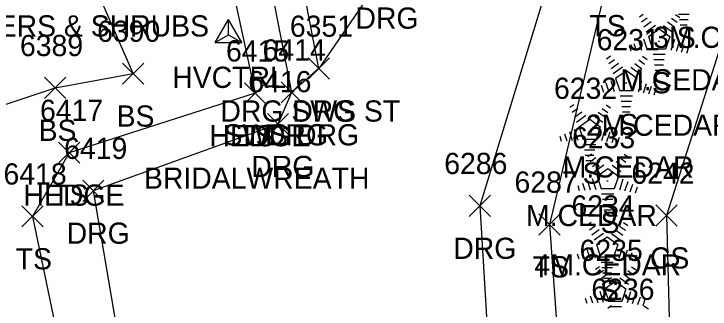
# Model space of a CAD drawing. Extents: x 1472233 to 1475777, y 540726 to 543442.
# Drawn here: x 1472325.6 to 1472391.2, y 541713.6 to 541741.4 of the extents above; entities that cross this region are included whole.
import ezdxf

# ---------------------------------------------------------------- set-up
doc = ezdxf.new("R2010")
doc.units = 0
for name, color, linetype in [('C_A', 7, 'Continuous'), ('CPSM', 7, 'Continuous'), ('L_A', 7, 'Continuous'), ('L_C', 7, 'Continuous'), ('L_I', 7, 'Continuous'), ('L_TIC', 7, 'Continuous'), ('LAHR', 7, 'Continuous'), ('LELB', 7, 'Continuous'), ('LTC', 7, 'Continuous'), ('R_A', 7, 'Continuous'), ('R_I', 7, 'Continuous'), ('R_TIC', 7, 'Continuous'), ('RDG', 7, 'Continuous'), ('RSW', 7, 'Continuous')]:
    doc.layers.add(name, color=color, linetype=linetype)

msp = doc.modelspace()

# ---------------------------------------------------------------- linework, layer by layer
at = {"layer": 'CPSM'}
for p, q in [((1472344.546, 541738.709), (1472345.796, 541740.875)), ((1472347.046, 541738.709), (1472345.796, 541740.875)), ((1472345.796, 541739.431), (1472345.796, 541740.875)), ((1472344.546, 541738.709), (1472345.796, 541739.431)), ((1472345.796, 541739.431), (1472345.796, 541739.431)), ((1472345.796, 541739.431), (1472347.046, 541738.709)), ((1472344.546, 541738.709), (1472347.046, 541738.709))]:
    msp.add_line(p, q, dxfattribs=at)
at = {"layer": 'L_TIC'}
for points in [[(1472335.805, 541734.776), (1472337.805, 541736.776)], [(1472337.805, 541734.776), (1472335.805, 541736.776)], [(1472328.455, 541733.43), (1472330.455, 541735.43)], [(1472330.455, 541733.43), (1472328.455, 541735.43)], [(1472347.293, 541732.92), (1472349.293, 541734.92)], [(1472349.293, 541732.92), (1472347.293, 541734.92)], [(1472347.293, 541732.92), (1472349.293, 541734.92)], [(1472349.293, 541732.92), (1472347.293, 541734.92)], [(1472329.773, 541727.319), (1472331.773, 541729.319)], [(1472331.773, 541727.319), (1472329.773, 541729.319)], [(1472329.773, 541727.319), (1472331.773, 541729.319)], [(1472331.773, 541727.319), (1472329.773, 541729.319)], [(1472326.33, 541721.315), (1472328.33, 541723.315)], [(1472328.33, 541721.315), (1472326.33, 541723.315)], [(1472386.055, 541721.394), (1472388.055, 541723.394)], [(1472388.055, 541721.394), (1472386.055, 541723.394)], [(1472375.043, 541720.552), (1472377.043, 541722.552)], [(1472377.043, 541720.552), (1472375.043, 541722.552)]]:
    msp.add_lwpolyline(points, dxfattribs=at)
at = {"layer": 'LAHR'}
msp.add_lwpolyline([(1472348.293, 541733.92), (1472330.773, 541728.319)], dxfattribs=at)
at = {"layer": 'LELB'}
for points in [[(1472436.391, 541801.492), (1472421.411, 541789.524), (1472401.228, 541772.53), (1472387.568, 541756.153), (1472381.39, 541744.301), (1472376.043, 541721.552), (1472378.297, 541690.008), (1472384.499, 541660.373), (1472385.476, 541622.917), (1472385.225, 541602.047), (1472389.103, 541583.282), (1472392.292, 541571.183), (1472400.004, 541561.87), (1472414.969, 541552.967), (1472430.215, 541550.577), (1472460.47, 541554.643), (1472482.624, 541564.355)], [(1472336.689, 541778.111), (1472339.985, 541776.003), (1472343.517, 541755.985), (1472348.293, 541733.92)], [(1472456.456, 541773.785), (1472441.328, 541777.081), (1472419.974, 541764.524), (1472393.226, 541741.709), (1472387.055, 541722.394), (1472387.861, 541691.003), (1472394.403, 541676.497), (1472412.587, 541665.699), (1472419.922, 541640.116), (1472426.411, 541618.317)], [(1472319.347, 541731.083), (1472329.455, 541734.43), (1472336.805, 541735.776), (1472331.369, 541748.277)], [(1472330.773, 541728.319), (1472327.33, 541722.315), (1472334.368, 541688.443), (1472342.801, 541683.722), (1472358.1, 541689.107)]]:
    msp.add_lwpolyline(points, dxfattribs=at)
at = {"layer": 'LTC'}
for p, q in [((1472384.498, 541741.122), (1472384.853, 541741.38)), ((1472384.708, 541740.657), (1472385.237, 541741.041)), ((1472387.525, 541741.014), (1472388.075, 541740.615)), ((1472387.897, 541741.363), (1472388.316, 541741.058)), ((1472389.184, 541741.36), (1472388.195, 541741.36)), ((1472384.917, 541740.191), (1472385.621, 541740.702)), ((1472385.127, 541739.725), (1472386.005, 541740.363)), ((1472387.154, 541740.666), (1472387.834, 541740.172)), ((1472389.1, 541740.86), (1472388.268, 541740.86)), ((1472389.016, 541740.36), (1472388.341, 541740.36)), ((1472385.352, 541739.27), (1472386.363, 541740.005)), ((1472386.363, 541740.005), (1472387.36, 541739.28)), ((1472386.783, 541740.318), (1472387.593, 541739.729)), ((1472384.897, 541739.051), (1472385.228, 541738.032)), ((1472385.352, 541739.27), (1472385.739, 541738.077)), ((1472387.36, 541739.28), (1472386.969, 541738.077)), ((1472383.531, 541738.401), (1472383.683, 541737.933)), ((1472383.986, 541738.618), (1472384.198, 541737.966)), ((1472384.442, 541738.835), (1472384.713, 541737.999)), ((1472387.798, 541739.009), (1472387.46, 541737.969)), ((1472388.242, 541738.758), (1472387.955, 541737.874)), ((1472388.687, 541738.508), (1472388.45, 541737.779)), ((1472386.969, 541738.077), (1472385.739, 541738.077)), ((1472389.131, 541738.258), (1472388.944, 541737.684)), ((1472381.41, 541737.186), (1472381.765, 541737.444)), ((1472381.62, 541736.721), (1472382.149, 541737.105)), ((1472384.437, 541737.078), (1472384.987, 541736.679)), ((1472384.809, 541737.427), (1472385.228, 541737.122)), ((1472386.931, 541737.577), (1472385.786, 541737.577)), ((1472386.847, 541737.077), (1472385.859, 541737.077)), ((1472381.829, 541736.255), (1472382.533, 541736.766)), ((1472382.039, 541735.789), (1472382.917, 541736.427)), ((1472384.067, 541736.73), (1472384.746, 541736.236)), ((1472386.763, 541736.577), (1472385.932, 541736.577)), ((1472382.264, 541735.334), (1472383.275, 541736.069)), ((1472383.275, 541736.069), (1472384.272, 541735.344)), ((1472383.695, 541736.382), (1472384.505, 541735.793)), ((1472386.679, 541736.077), (1472386.004, 541736.077)), ((1472381.809, 541735.115), (1472382.14, 541734.096)), ((1472382.264, 541735.334), (1472382.651, 541734.141)), ((1472384.272, 541735.344), (1472383.881, 541734.141)), ((1472380.443, 541734.465), (1472380.595, 541733.998)), ((1472380.898, 541734.682), (1472381.11, 541734.03)), ((1472381.354, 541734.899), (1472381.625, 541734.063)), ((1472384.71, 541735.073), (1472384.372, 541734.033)), ((1472385.154, 541734.823), (1472384.867, 541733.938)), ((1472385.599, 541734.573), (1472385.362, 541733.843)), ((1472383.881, 541734.141), (1472382.651, 541734.141)), ((1472386.043, 541734.322), (1472385.857, 541733.748)), ((1472383.843, 541733.641), (1472382.698, 541733.641)), ((1472383.759, 541733.141), (1472382.771, 541733.141)), ((1472377.96, 541732.606), (1472378.315, 541732.863)), ((1472378.17, 541732.14), (1472378.699, 541732.524)), ((1472380.987, 541732.498), (1472381.537, 541732.099)), ((1472381.359, 541732.846), (1472381.778, 541732.542)), ((1472383.675, 541732.641), (1472382.844, 541732.641)), ((1472378.379, 541731.674), (1472379.083, 541732.186)), ((1472378.589, 541731.209), (1472379.467, 541731.847)), ((1472380.617, 541732.149), (1472381.296, 541731.656)), ((1472383.592, 541732.141), (1472382.917, 541732.141)), ((1472378.814, 541730.754), (1472379.825, 541731.488)), ((1472379.825, 541731.488), (1472380.822, 541730.763)), ((1472380.245, 541731.801), (1472381.055, 541731.212)), ((1472378.359, 541730.534), (1472378.69, 541729.515)), ((1472378.814, 541730.754), (1472379.201, 541729.56)), ((1472380.822, 541730.763), (1472380.431, 541729.56)), ((1472376.993, 541729.885), (1472377.145, 541729.417)), ((1472377.448, 541730.102), (1472377.66, 541729.45)), ((1472377.904, 541730.318), (1472378.175, 541729.483)), ((1472381.26, 541730.492), (1472380.922, 541729.453)), ((1472381.704, 541730.242), (1472381.417, 541729.357)), ((1472382.149, 541729.992), (1472381.912, 541729.262)), ((1472380.431, 541729.56), (1472379.201, 541729.56)), ((1472382.593, 541729.742), (1472382.407, 541729.167)), ((1472380.393, 541729.06), (1472379.248, 541729.06)), ((1472380.309, 541728.56), (1472379.321, 541728.56)), ((1472380.225, 541728.06), (1472379.394, 541728.06)), ((1472379.657, 541727.948), (1472380.011, 541728.205)), ((1472383.055, 541728.188), (1472383.474, 541727.883)), ((1472380.142, 541727.56), (1472379.467, 541727.56)), ((1472379.866, 541727.482), (1472380.395, 541727.866)), ((1472380.076, 541727.016), (1472380.78, 541727.528)), ((1472382.313, 541727.491), (1472382.992, 541726.998)), ((1472382.684, 541727.84), (1472383.233, 541727.44)), ((1472380.285, 541726.55), (1472381.164, 541727.188)), ((1472380.51, 541726.095), (1472381.522, 541726.83)), ((1472381.522, 541726.83), (1472382.519, 541726.105)), ((1472381.942, 541727.143), (1472382.751, 541726.554)), ((1472380.51, 541726.095), (1472380.897, 541724.902)), ((1472382.519, 541726.105), (1472382.127, 541724.902)), ((1472379.145, 541725.443), (1472379.356, 541724.792)), ((1472379.6, 541725.66), (1472379.871, 541724.825)), ((1472380.055, 541725.876), (1472380.386, 541724.857)), ((1472382.956, 541725.834), (1472382.618, 541724.795)), ((1472383.401, 541725.584), (1472383.113, 541724.699)), ((1472383.845, 541725.334), (1472383.608, 541724.604)), ((1472378.689, 541725.227), (1472378.841, 541724.759)), ((1472382.127, 541724.902), (1472380.897, 541724.902)), ((1472384.29, 541725.083), (1472384.103, 541724.509)), ((1472382.089, 541724.402), (1472380.945, 541724.402)), ((1472382.005, 541723.902), (1472381.017, 541723.902)), ((1472381.922, 541723.402), (1472381.09, 541723.402)), ((1472381.838, 541722.902), (1472381.163, 541722.902)), ((1472379.604, 541721.505), (1472379.959, 541721.762)), ((1472379.814, 541721.039), (1472380.343, 541721.423)), ((1472382.631, 541721.397), (1472383.181, 541720.998)), ((1472383.002, 541721.745), (1472383.422, 541721.441)), ((1472380.023, 541720.573), (1472380.727, 541721.085)), ((1472380.233, 541720.108), (1472381.111, 541720.746)), ((1472381.889, 541720.7), (1472382.699, 541720.111)), ((1472382.26, 541721.048), (1472382.94, 541720.555)), ((1472380.457, 541719.653), (1472381.469, 541720.387)), ((1472381.469, 541720.387), (1472382.466, 541719.662)), ((1472380.003, 541719.433), (1472380.334, 541718.414)), ((1472380.457, 541719.653), (1472380.845, 541718.459)), ((1472382.466, 541719.662), (1472382.075, 541718.459)), ((1472382.904, 541719.391), (1472382.566, 541718.352)), ((1472378.637, 541718.784), (1472378.789, 541718.316)), ((1472379.092, 541719.001), (1472379.304, 541718.349)), ((1472379.547, 541719.217), (1472379.819, 541718.382)), ((1472383.348, 541719.141), (1472383.061, 541718.256)), ((1472383.793, 541718.891), (1472383.556, 541718.161)), ((1472382.075, 541718.459), (1472380.845, 541718.459)), ((1472384.237, 541718.641), (1472384.05, 541718.066)), ((1472380.373, 541717.323), (1472380.728, 541717.581)), ((1472382.037, 541717.959), (1472380.892, 541717.959)), ((1472381.953, 541717.459), (1472380.965, 541717.459)), ((1472383.771, 541717.564), (1472384.191, 541717.259)), ((1472380.583, 541716.858), (1472381.112, 541717.242)), ((1472380.792, 541716.392), (1472381.496, 541716.903)), ((1472381.869, 541716.959), (1472381.037, 541716.959)), ((1472383.029, 541716.867), (1472383.709, 541716.373)), ((1472383.4, 541717.215), (1472383.95, 541716.816)), ((1472381.002, 541715.926), (1472381.88, 541716.564)), ((1472381.785, 541716.459), (1472381.11, 541716.459)), ((1472381.226, 541715.471), (1472382.238, 541716.206)), ((1472382.238, 541716.206), (1472383.235, 541715.481)), ((1472382.658, 541716.519), (1472383.468, 541715.93)), ((1472381.226, 541715.471), (1472381.614, 541714.278)), ((1472383.235, 541715.481), (1472382.844, 541714.278)), ((1472379.861, 541714.819), (1472380.073, 541714.168)), ((1472380.316, 541715.036), (1472380.588, 541714.2)), ((1472380.772, 541715.252), (1472381.103, 541714.233)), ((1472383.673, 541715.21), (1472383.335, 541714.17)), ((1472384.117, 541714.96), (1472383.83, 541714.075)), ((1472379.406, 541714.603), (1472379.558, 541714.135)), ((1472382.844, 541714.278), (1472381.614, 541714.278)), ((1472384.562, 541714.71), (1472384.325, 541713.98)), ((1472385.006, 541714.459), (1472384.819, 541713.885)), ((1472381.532, 541713.649), (1472381.887, 541713.906)), ((1472382.806, 541713.778), (1472381.661, 541713.778)), ((1472384.93, 541713.889), (1472385.349, 541713.585))]:
    msp.add_line(p, q, dxfattribs=at)
at = {"layer": 'R_TIC'}
for points in [[(1472353.31, 541735.251), (1472355.31, 541737.251)], [(1472355.31, 541735.251), (1472353.31, 541737.251)], [(1472353.31, 541735.251), (1472355.31, 541737.251)], [(1472355.31, 541735.251), (1472353.31, 541737.251)], [(1472350.736, 541733.008), (1472352.736, 541735.008)], [(1472352.736, 541733.008), (1472350.736, 541735.008)], [(1472350.736, 541733.008), (1472352.736, 541735.008)], [(1472352.736, 541733.008), (1472350.736, 541735.008)], [(1472349.45, 541730.024), (1472351.45, 541732.024)], [(1472351.45, 541730.024), (1472349.45, 541732.024)], [(1472332.053, 541723.73), (1472334.053, 541725.73)], [(1472334.053, 541723.73), (1472332.053, 541725.73)], [(1472368.478, 541722.305), (1472370.478, 541724.305)], [(1472370.478, 541722.305), (1472368.478, 541724.305)]]:
    msp.add_lwpolyline(points, dxfattribs=at)
at = {"layer": 'RDG'}
for points in [[(1472443.664, 541851.187), (1472441.122, 541840.862), (1472437.139, 541827.961), (1472432.888, 541822.313), (1472422.112, 541812.207), (1472405.366, 541796.547), (1472387.727, 541780.283), (1472366.614, 541755.489), (1472360.262, 541745.014), (1472354.31, 541736.251), (1472351.736, 541734.008), (1472350.45, 541731.024), (1472333.053, 541724.73), (1472338.858, 541690.593), (1472353.84, 541691.596), (1472358.1, 541689.107), (1472361.8, 541678.978), (1472366.888, 541639.978)], [(1472458.476, 541813.052), (1472448.097, 541812.754), (1472433.314, 541805.765), (1472418.45, 541793.865), (1472396.988, 541775.056), (1472383.579, 541758.581), (1472377.023, 541748.043), (1472369.478, 541723.305), (1472371.476, 541689.861), (1472374.14, 541661.129), (1472378.683, 541621.312), (1472380, 541600.019), (1472383.251, 541579.962), (1472388.389, 541568.427), (1472396.047, 541559.533), (1472413.232, 541549.278), (1472429.514, 541545.681), (1472464.232, 541550.412), (1472485.309, 541561.603)]]:
    msp.add_lwpolyline(points, dxfattribs=at)
at = {"layer": 'RSW'}
msp.add_lwpolyline([(1472354.31, 541736.251), (1472348.923, 541764.205), (1472344.992, 541784.034), (1472342.326, 541783.705), (1472347.161, 541757.349), (1472351.736, 541734.008)], dxfattribs=at)

# ---------------------------------------------------------------- texts
at = {"layer": 'C_A'}
msp.add_text('HVCTRL', height=2, dxfattribs=at).set_placement((1472340.489, 541734.431))
at = {"layer": 'L_A'}
for s, p in [('TS', (1472379.799, 541739.301)), ('S', (1472388.025, 541738.197)), ('S', (1472385.689, 541733.914)), ('BS', (1472335.246, 541730.776)), ('S', (1472382.601, 541729.978)), ('BS', (1472327.896, 541729.43)), ('HEDGE', (1472343.994, 541728.92)), ('TS', (1472346.703, 541728.92)), ('S', (1472379.151, 541725.398)), ('HEDGE', (1472326.473, 541723.319)), ('TS', (1472329.182, 541723.319)), ('S', (1472380.847, 541720.739)), ('CS', (1472385.496, 541717.394)), ('TS', (1472325.739, 541717.315)), ('TS', (1472374.452, 541716.552)), ('S', (1472380.795, 541714.297))]:
    msp.add_text(s, height=2, dxfattribs=at).set_placement(p)
at = {"layer": 'L_C'}
for s, p in [('FLOWERS & SHRUBS', (1472316.313, 541739.277)), ('FLOWERS & SHRUBS', (1472316.313, 541739.277)), ('3M.CEDAR', (1472385.802, 541738.205)), ('M.CEDAR', (1472382.695, 541734.197)), ('2M.CEDAR', (1472379.461, 541729.914)), ('M.CEDAR', (1472377.27, 541725.978)), ('BRIDALWREATH', (1472337.821, 541724.92)), ('M.CEDAR', (1472373.82, 541721.398)), ('4M.CEDAR', (1472374.619, 541716.739))]:
    msp.add_text(s, height=2, dxfattribs=at).set_placement(p)
at = {"layer": 'L_I'}
for s, p in [('6390', (1472333.411, 541738.776)), ('6231', (1472380.475, 541737.978)), ('6389', (1472326.14, 541737.43)), ('6415', (1472345.553, 541736.92)), ('6415', (1472345.553, 541736.92)), ('6232', (1472376.458, 541733.398)), ('6417', (1472328.032, 541731.319)), ('6417', (1472328.032, 541731.319)), ('6233', (1472378.154, 541728.739)), ('6418', (1472324.59, 541725.315)), ('6242', (1472383.748, 541725.394)), ('6287', (1472372.736, 541724.552)), ('6234', (1472378.102, 541722.297)), ('6235', (1472378.871, 541718.115)), ('6236', (1472379.975, 541714.441))]:
    msp.add_text(s, height=2, dxfattribs=at).set_placement(p)
at = {"layer": 'LTC'}
for p in [(1472386.246, 541739.018), (1472383.158, 541735.082), (1472379.708, 541730.502), (1472381.404, 541725.843), (1472381.352, 541719.401), (1472382.121, 541715.219)]:
    msp.add_text('.', height=1.037, rotation=270, dxfattribs=at).set_placement(p)
at = {"layer": 'R_A'}
for s, p in [('DRG', (1472357.75, 541740.014)), ('DRG SWS ST', (1472345.027, 541731.251)), ('DRG', (1472351.798, 541731.251)), ('SWS DRG', (1472345.318, 541729.008)), ('DRG', (1472349.224, 541729.008)), ('DRG', (1472347.938, 541726.024)), ('DRG', (1472330.541, 541719.73)), ('DRG', (1472366.966, 541718.305))]:
    msp.add_text(s, height=2, dxfattribs=at).set_placement(p)
at = {"layer": 'R_I'}
for s, p in [('6351', (1472351.57, 541739.251)), ('6351', (1472351.57, 541739.251)), ('6414', (1472348.995, 541737.008)), ('6414', (1472348.995, 541737.008)), ('6416', (1472347.655, 541734.024)), ('6419', (1472330.305, 541727.73)), ('6286', (1472366.116, 541726.305))]:
    msp.add_text(s, height=2, dxfattribs=at).set_placement(p)

doc.saveas('drawing.dxf')
